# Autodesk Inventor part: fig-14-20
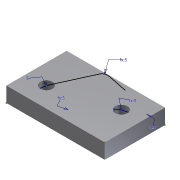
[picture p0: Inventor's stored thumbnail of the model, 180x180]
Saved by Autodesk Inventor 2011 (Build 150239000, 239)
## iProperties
Created: 2005-04
Part Number: fig-14-20
Document SubType Name: Modeling
Designer: CADCIM
Density: 1 g/cm^3
Author: CADCIM
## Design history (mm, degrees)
sketch "Sketch1"
  geometry: L1 (-34.758, -22.218)-(30.545, -22.218); L2 (30.545, -22.218)-(30.545, 17.782); L3 (30.545, 17.782)-(-34.758, 17.782); L4 (-34.758, 17.782)-(-34.758, -22.218)
  constraints: 8 end point, 2 parallel, 1 horizontal, 1 perpendicular
  dimensions: "d0" = 65.30359 distance of L2.end L3.end; "d1" = 40 distance of L1.end L2.end
extrude "Extrusion1" new body sketch "Sketch1" distance "d2" = 10; taper "d3" = 0 deg
hole "Hole1" diameter "d13" = 8; stored, may be unused: countersink angle "d17" = 90 deg, drill point angle "d19" = 118 deg; dims "d11" = 13.458, "d12" = 13.14, "d14" = 6, "d15" = 4, "d16" = 2, "d18" = 15
hole "Hole2" diameter "d22" = 8; stored, may be unused: countersink angle "d26" = 90 deg, drill point angle "d28" = 118 deg; dims "d20" = 13.299, "d21" = 15.705, "d23" = 6, "d24" = 4, "d25" = 2, "d27" = 15
sketch "3D Sketch2" dims "d29" = 5, "d30" = 5 (= d29), "d31" = 5 (= d29), "d32" = 5 (= d29), "d33" = 5 (= d29)
body "Solid1"
other parameters: "LEN" = 1 [user parameter]
